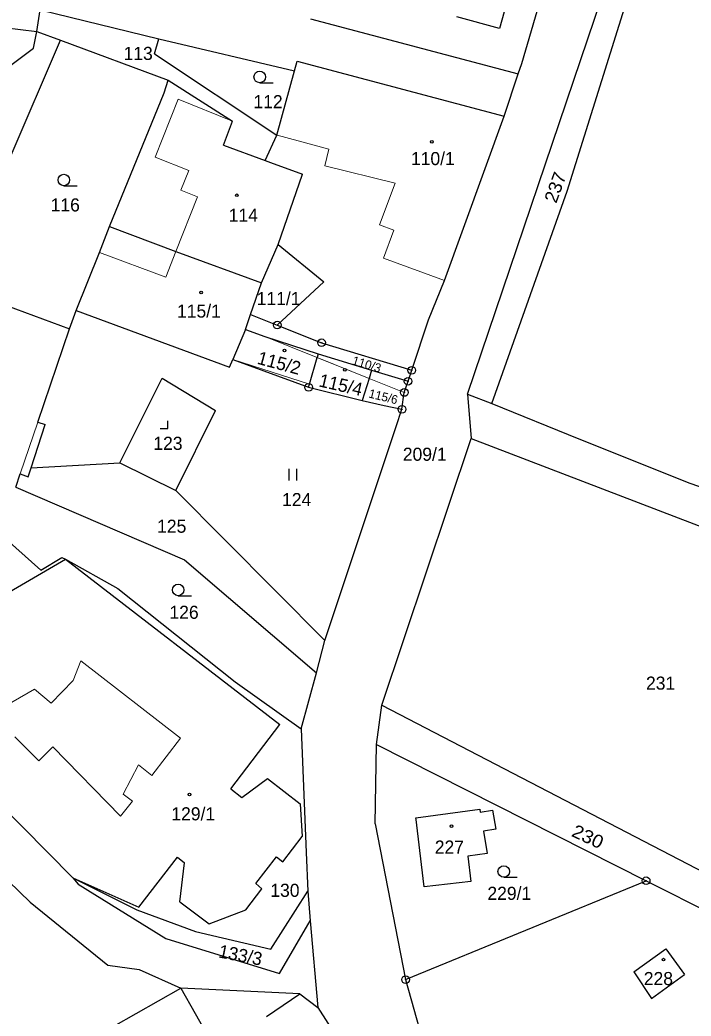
# Model space of a CAD drawing. Extents: x -633485 to -630509, y -1112692 to -1108818.
# Drawn here: x -631830.6 to -631743.5, y -1111847.5 to -1111718.1 of the extents above; entities that cross this region are included whole.
import ezdxf
from ezdxf.enums import TextEntityAlignment as Align

# ---------------------------------------------------------------- set-up
doc = ezdxf.new("R2010")
doc.units = 0
doc.header["$LTSCALE"] = 0.68
for name, color, linetype, lineweight in [('1', 7, 'Continuous', 25), ('13', 7, 'Continuous', 13), ('3', 7, 'Continuous', 25), ('4', 7, 'Continuous', 13), ('5', 7, 'Continuous', 25), ('8', 7, 'Continuous', 25)]:
    doc.layers.add(name, color=color, linetype=linetype, lineweight=lineweight)
doc.layers.add('2', color=7, linetype='Continuous')

msp = doc.modelspace()

# ---------------------------------------------------------------- linework, layer by layer
at = {"layer": '1'}
for p, q in [((-631772.51, -1111766.65), (-631751.2, -1111703.81)), ((-631765.44, -1111723.7), (-631759.7, -1111704.04)), ((-631759.55, -1111740.28), (-631748.3, -1111704.38)), ((-631765.54, -1111709.03), (-631768.33, -1111719.18)), ((-631828.44, -1111719.54), (-631827.99, -1111716.75)), ((-631827.99, -1111716.75), (-631812.56, -1111720.53)), ((-631768.33, -1111719.18), (-631773.86, -1111717.66)), ((-631832.68, -1111719.04), (-631828.44, -1111719.54)), ((-631828.85, -1111721.71), (-631828.44, -1111719.54)), ((-631828.44, -1111719.54), (-631825.35, -1111720.7)), ((-631831.89, -1111735.93), (-631825.35, -1111720.7)), ((-631825.35, -1111720.7), (-631811.37, -1111725.89)), ((-631813.16, -1111722.44), (-631812.56, -1111720.53)), ((-631812.56, -1111720.53), (-631794.95, -1111724.66)), ((-631833.63, -1111725.28), (-631828.85, -1111721.71)), ((-631813.16, -1111722.44), (-631797.24, -1111733.03)), ((-631794.95, -1111724.66), (-631794.63, -1111723.4)), ((-631794.63, -1111723.4), (-631767.71, -1111730.55)), ((-631797.24, -1111733.03), (-631794.95, -1111724.66)), ((-631811.87, -1111727.54), (-631811.37, -1111725.89)), ((-631811.37, -1111725.89), (-631803.02, -1111731.2)), ((-631767.71, -1111730.55), (-631765.89, -1111725.06)), ((-631818.97, -1111744.91), (-631811.87, -1111727.54)), ((-631804.17, -1111734.31), (-631803.02, -1111731.2)), ((-631775.47, -1111751.92), (-631767.71, -1111730.55)), ((-631798.77, -1111736.3), (-631797.24, -1111733.03)), ((-631804.17, -1111734.31), (-631798.77, -1111736.3)), ((-631798.77, -1111736.3), (-631798.08, -1111736.56)), ((-631798.08, -1111736.56), (-631793.92, -1111738.09)), ((-631797.1, -1111747.25), (-631793.92, -1111738.09)), ((-631769.32, -1111767.88), (-631759.55, -1111740.28)), ((-631820.3, -1111748.26), (-631818.97, -1111744.91)), ((-631818.97, -1111744.91), (-631810.37, -1111748.16)), ((-631799.24, -1111752.22), (-631797.1, -1111747.25)), ((-631797.1, -1111747.25), (-631791.17, -1111752.06)), ((-631823.32, -1111755.79), (-631820.3, -1111748.26)), ((-631810.37, -1111748.16), (-631799.24, -1111752.22)), ((-631777.54, -1111757.03), (-631775.47, -1111751.92)), ((-631839.35, -1111752.55), (-631824.16, -1111758.2)), ((-631800.66, -1111756.33), (-631799.24, -1111752.22)), ((-631797.2, -1111757.7), (-631791.17, -1111752.06)), ((-631824.16, -1111758.2), (-631823.32, -1111755.79)), ((-631823.32, -1111755.79), (-631803.4, -1111763.16)), ((-631801.33, -1111758.29), (-631800.66, -1111756.33)), ((-631800.66, -1111756.33), (-631797.2, -1111757.7)), ((-631779.73, -1111763.57), (-631777.54, -1111757.03)), ((-631828.28, -1111770.29), (-631824.16, -1111758.2)), ((-631801.33, -1111758.29), (-631802.95, -1111762.15)), ((-631801.33, -1111758.29), (-631798.8, -1111759.2)), ((-631798.8, -1111759.2), (-631791.88, -1111761.42)), ((-631803.4, -1111763.16), (-631802.95, -1111762.15)), ((-631802.95, -1111762.15), (-631793.12, -1111765.78)), ((-631793, -1111765.37), (-631792.02, -1111761.92)), ((-631791.88, -1111761.42), (-631792.02, -1111761.92)), ((-631791.88, -1111761.42), (-631784.94, -1111763.54)), ((-631784.94, -1111763.54), (-631785.27, -1111764.62)), ((-631784.94, -1111763.54), (-631780.21, -1111764.99)), ((-631780.21, -1111764.99), (-631779.73, -1111763.57)), ((-631817.63, -1111775.61), (-631812.16, -1111764.59)), ((-631812.16, -1111764.59), (-631805.23, -1111768.78)), ((-631785.27, -1111764.62), (-631786.16, -1111767.48)), ((-631793.12, -1111765.78), (-631793, -1111765.37)), ((-631793.12, -1111765.78), (-631786.16, -1111767.48)), ((-631780.7, -1111766.45), (-631780.21, -1111764.99)), ((-631781, -1111768.64), (-631780.7, -1111766.45)), ((-631772.51, -1111766.65), (-631772.03, -1111772.41)), ((-631772.51, -1111766.65), (-631769.32, -1111767.88)), ((-631810.39, -1111779.2), (-631805.23, -1111768.78)), ((-631781.76, -1111770.87), (-631781, -1111768.64)), ((-631769.32, -1111767.88), (-631758.05, -1111772.47)), ((-631829.16, -1111776.26), (-631827.34, -1111770.61)), ((-631828.28, -1111770.29), (-631827.34, -1111770.61)), ((-631791.02, -1111798.69), (-631781.76, -1111770.87)), ((-631783.6, -1111807.07), (-631772.03, -1111772.41)), ((-631772.03, -1111772.41), (-631712.92, -1111795.09)), ((-631758.05, -1111772.47), (-631743.6, -1111778.23)), ((-631829.54, -1111777.39), (-631829.16, -1111776.26)), ((-631829.16, -1111776.26), (-631817.63, -1111775.61)), ((-631817.63, -1111775.61), (-631810.39, -1111779.2)), ((-631831.15, -1111778.74), (-631830.57, -1111777.04)), ((-631830.57, -1111777.04), (-631829.54, -1111777.39)), ((-631831.15, -1111778.74), (-631809.24, -1111788.21)), ((-631743.6, -1111778.23), (-631729.98, -1111783.03)), ((-631810.39, -1111779.2), (-631791.02, -1111798.69)), ((-631833.23, -1111784.83), (-631827.9, -1111789.52)), ((-631834.92, -1111794.04), (-631824.7, -1111788.1)), ((-631827.9, -1111789.52), (-631825.16, -1111787.88)), ((-631825.16, -1111787.88), (-631824.7, -1111788.1)), ((-631824.7, -1111788.1), (-631817.9, -1111791.9)), ((-631824.7, -1111788.1), (-631796.86, -1111809.57)), ((-631809.24, -1111788.21), (-631792.1, -1111802.88)), ((-631817.9, -1111791.9), (-631802.68, -1111804.05)), ((-631792.1, -1111802.88), (-631791.02, -1111798.69)), ((-631794.11, -1111810.15), (-631792.1, -1111802.88)), ((-631802.68, -1111804.05), (-631794.11, -1111810.15)), ((-631784.3, -1111812.2), (-631783.6, -1111807.07)), ((-631783.6, -1111807.07), (-631724.6, -1111837.74)), ((-631803.23, -1111817.92), (-631796.86, -1111809.57)), ((-631794.11, -1111810.15), (-631793.45, -1111826.19)), ((-631784.5, -1111822.5), (-631784.3, -1111812.2)), ((-631784.3, -1111812.2), (-631749.29, -1111829.88)), ((-631836.65, -1111816.48), (-631823.73, -1111829.48)), ((-631801.79, -1111819.05), (-631798.45, -1111816.58)), ((-631798.45, -1111816.58), (-631794.21, -1111819.89)), ((-631803.23, -1111817.92), (-631801.79, -1111819.05)), ((-631842.28, -1111820.13), (-631829.28, -1111832.66)), ((-631794.21, -1111819.89), (-631793.97, -1111824.14)), ((-631784.5, -1111822.5), (-631780.53, -1111842.73)), ((-631796.48, -1111827.41), (-631793.97, -1111824.14)), ((-631815.19, -1111833.33), (-631810.16, -1111826.8)), ((-631810.16, -1111826.8), (-631809.23, -1111827.56)), ((-631799.99, -1111830.25), (-631797.31, -1111826.77)), ((-631797.31, -1111826.77), (-631796.48, -1111827.41)), ((-631793.45, -1111826.19), (-631793.24, -1111831.25)), ((-631809.83, -1111832.62), (-631809.23, -1111827.56)), ((-631823.73, -1111829.48), (-631815.19, -1111833.33)), ((-631823.73, -1111829.48), (-631815.44, -1111833.68)), ((-631823.73, -1111829.48), (-631823.07, -1111830.32)), ((-631823.07, -1111830.32), (-631811.69, -1111837.38)), ((-631799.99, -1111830.25), (-631799.21, -1111830.92)), ((-631780.53, -1111842.73), (-631749.29, -1111829.88)), ((-631749.29, -1111829.88), (-631726.57, -1111841.36)), ((-631801.3, -1111833.67), (-631799.21, -1111830.92)), ((-631798.03, -1111838.76), (-631793.24, -1111831.25)), ((-631793.24, -1111831.25), (-631792.91, -1111835.07)), ((-631829.28, -1111832.66), (-631819.22, -1111840.85)), ((-631809.83, -1111832.62), (-631806.06, -1111835.48)), ((-631815.44, -1111833.68), (-631807.8, -1111836.49)), ((-631806.06, -1111835.48), (-631801.3, -1111833.67)), ((-631796.9, -1111841.92), (-631792.91, -1111835.07)), ((-631792.91, -1111835.07), (-631791.93, -1111846.33)), ((-631811.69, -1111837.38), (-631796.9, -1111841.92)), ((-631807.8, -1111836.49), (-631798.03, -1111838.76)), ((-631750.88, -1111841.73), (-631746.72, -1111838.74)), ((-631746.72, -1111838.74), (-631744.32, -1111842.08)), ((-631819.22, -1111840.85), (-631815.14, -1111841.43)), ((-631815.14, -1111841.43), (-631809.73, -1111843.82)), ((-631750.88, -1111841.73), (-631748.59, -1111845.18)), ((-631748.59, -1111845.18), (-631744.32, -1111842.08)), ((-631821.81, -1111850.68), (-631809.73, -1111843.82)), ((-631794.26, -1111844.56), (-631809.73, -1111843.82)), ((-631809.73, -1111843.82), (-631805.13, -1111851.95)), ((-631780.53, -1111842.73), (-631772.13, -1111872.41)), ((-631798.6, -1111847.51), (-631794.26, -1111844.56)), ((-631794.26, -1111844.56), (-631791.93, -1111846.33)), ((-631791.93, -1111846.33), (-631785.34, -1111856.57))]:
    msp.add_line(p, q, dxfattribs=at)
for points in [[(-631792.9, -1111717.93), (-631765.89, -1111725.06), (-631765.44, -1111723.7)], [(-631797.2, -1111757.7), (-631791.44, -1111759.99), (-631779.73, -1111763.57)], [(-631786.16, -1111767.48), (-631783.3, -1111768.14), (-631781, -1111768.64)], [(-631779.18, -1111821.69), (-631770.91, -1111820.6), (-631770.85, -1111820.96), (-631769.24, -1111820.69), (-631768.82, -1111823.17), (-631770.43, -1111823.44), (-631769.94, -1111826.36), (-631772.44, -1111826.67), (-631772.06, -1111829.98), (-631778.1, -1111830.66), (-631778.67, -1111825.96)], [(-631778.67, -1111825.96), (-631779.15, -1111821.92), (-631779.18, -1111821.69)]]:
    msp.add_lwpolyline(points, dxfattribs=at)
at = {"layer": '13'}
for points in [[(-631798.8, -1111759.2), (-631785.27, -1111764.62), (-631780.7, -1111766.45), (-631780.21, -1111764.99), (-631784.94, -1111763.54), (-631791.88, -1111761.42)], [(-631792.02, -1111761.92), (-631785.27, -1111764.62), (-631780.7, -1111766.45), (-631780.21, -1111764.99), (-631784.94, -1111763.54), (-631791.88, -1111761.42)]]:
    msp.add_lwpolyline(points, close=True, dxfattribs=at)
at = {"layer": '3'}
for p, q in [((-631799.473, -1111726.21), (-631797.723, -1111726.21)), ((-631824.913, -1111739.6), (-631823.163, -1111739.6)), ((-631795.641, -1111777.89), (-631795.641, -1111776.39)), ((-631794.64, -1111777.89), (-631794.64, -1111776.39)), ((-631810.073, -1111792.85), (-631808.323, -1111792.85)), ((-631767.783, -1111829.43), (-631766.033, -1111829.43))]:
    msp.add_line(p, q, dxfattribs=at)
msp.add_lwpolyline([(-631812.401, -1111771.12), (-631811.4, -1111771.12), (-631811.4, -1111770.12)], dxfattribs=at)
for centre in [(-631799.4729, -1111725.4598), (-631824.9129, -1111738.8498), (-631810.0729, -1111792.0998), (-631767.7829, -1111828.6798)]:
    msp.add_circle(centre, 0.75, dxfattribs=at)
at = {"layer": '4'}
for p, q in [((-631813.06, -1111735.89), (-631810.07, -1111728.34)), ((-631810.07, -1111728.34), (-631803.02, -1111731.2)), ((-631797.24, -1111733.03), (-631796.55, -1111733.22)), ((-631796.55, -1111733.22), (-631790.51, -1111734.85)), ((-631791.03, -1111737.02), (-631790.51, -1111734.85)), ((-631813.06, -1111735.89), (-631808.69, -1111737.62)), ((-631809.7, -1111740.17), (-631808.69, -1111737.62)), ((-631791.03, -1111737.02), (-631781.9, -1111739.26)), ((-631809.7, -1111740.17), (-631807.55, -1111741.02)), ((-631783.9, -1111744.68), (-631781.9, -1111739.26)), ((-631810.37, -1111748.16), (-631807.55, -1111741.02)), ((-631783.9, -1111744.68), (-631782.04, -1111745.37)), ((-631783.38, -1111748.99), (-631782.04, -1111745.37)), ((-631820.3, -1111748.26), (-631811.67, -1111751.46)), ((-631811.67, -1111751.46), (-631810.37, -1111748.16)), ((-631783.38, -1111748.99), (-631775.47, -1111751.92)), ((-631802.95, -1111762.15), (-631793, -1111765.37)), ((-631830.57, -1111777.04), (-631828.28, -1111770.29)), ((-631823.71, -1111803.86), (-631822.69, -1111801.33)), ((-631822.69, -1111801.33), (-631809.76, -1111811.35)), ((-631838.83, -1111810.84), (-631828.73, -1111805)), ((-631828.73, -1111805), (-631826.58, -1111806.82)), ((-631826.58, -1111806.82), (-631823.71, -1111803.86)), ((-631831.3, -1111811.18), (-631828.18, -1111814.3)), ((-631813.48, -1111816.21), (-631809.76, -1111811.35)), ((-631828.18, -1111814.3), (-631826.35, -1111812.49)), ((-631826.35, -1111812.49), (-631817.56, -1111821.49)), ((-631817.21, -1111818.62), (-631815.2, -1111814.83)), ((-631815.2, -1111814.83), (-631813.48, -1111816.21)), ((-631817.21, -1111818.62), (-631816.01, -1111819.53)), ((-631817.56, -1111821.49), (-631816.01, -1111819.53))]:
    msp.add_line(p, q, dxfattribs=at)
at = {"layer": '5'}
for centre in [(-631777.1168, -1111733.8792), (-631802.4368, -1111740.8392), (-631807.0968, -1111753.4592), (-631796.2668, -1111760.9892), (-631788.4268, -1111763.5192), (-631808.5868, -1111818.6692), (-631774.5668, -1111822.7892), (-631747.0268, -1111840.1292)]:
    msp.add_circle(centre, 0.175, dxfattribs=at)
at = {"layer": '8'}
for centre, radius in [((-631797.2, -1111757.6999), 0.5), ((-631797.2, -1111757.6999), 0.0303), ((-631791.44, -1111759.9899), 0.5), ((-631791.44, -1111759.9899), 0.0303), ((-631779.73, -1111763.5699), 0.5), ((-631779.73, -1111763.5699), 0.0303), ((-631780.21, -1111764.9899), 0.5), ((-631793.12, -1111765.7799), 0.5), ((-631793.12, -1111765.7799), 0.0303), ((-631780.7, -1111766.4499), 0.5), ((-631780.21, -1111764.9899), 0.0303), ((-631780.7, -1111766.4499), 0.0303), ((-631781, -1111768.6399), 0.5), ((-631781, -1111768.6399), 0.0303), ((-631749.29, -1111829.8799), 0.5), ((-631749.29, -1111829.8799), 0.0303), ((-631780.53, -1111842.7299), 0.5), ((-631780.53, -1111842.7299), 0.0303)]:
    msp.add_circle(centre, radius, dxfattribs=at)

# ---------------------------------------------------------------- texts
at = {"layer": '2'}
for s, p in [('113', (-631817.16, -1111723.255)), ('112', (-631800.29, -1111729.525)), ('116', (-631826.63, -1111742.935)), ('114', (-631803.5, -1111744.265)), ('123', (-631813.29, -1111773.905)), ('209/1', (-631780.89, -1111775.325)), ('124', (-631796.57, -1111781.215)), ('125', (-631812.8, -1111784.675)), ('126', (-631811.2, -1111795.855)), ('231', (-631749.31, -1111805.055)), ('129/1', (-631810.95, -1111822.035)), ('227', (-631776.74, -1111826.355)), ('130', (-631798.1, -1111831.975))]:
    msp.add_text(s, height=1.7, dxfattribs=at).set_placement(p)
for s, p in [('110/1', (-631776.99, -1111736.915)), ('111/1', (-631797.02, -1111755.095)), ('115/1', (-631807.37, -1111756.725)), ('229/1', (-631767.06, -1111832.365)), ('228', (-631747.699, -1111843.435))]:
    msp.add_text(s, height=1.7, dxfattribs=at).set_placement(p, align=Align.CENTER)
for s, rotation, width, p in [('237', 70, 1.05, (-631760.97, -1111741.965)), ('230', 335, 1.1, (-631759.109, -1111824.035))]:
    msp.add_text(s, height=1.7, rotation=rotation, dxfattribs=dict(at, width=width)).set_placement(p)
for s, height, rotation, p in [('115/2', 1.7, 345, (-631797.168, -1111763.4399)), ('110/3', 1.139, 343, (-631785.7385, -1111763.3373)), ('115/4', 1.7, 347, (-631789.1282, -1111766.2865)), ('115/6', 1.139, 346, (-631783.5578, -1111767.5433))]:
    msp.add_text(s, height=height, rotation=rotation, dxfattribs=at).set_placement(p, align=Align.CENTER)
msp.add_text('133/3', height=1.7, rotation=349, dxfattribs=at).set_placement((-631804.921, -1111839.827))

doc.saveas('drawing.dxf')
